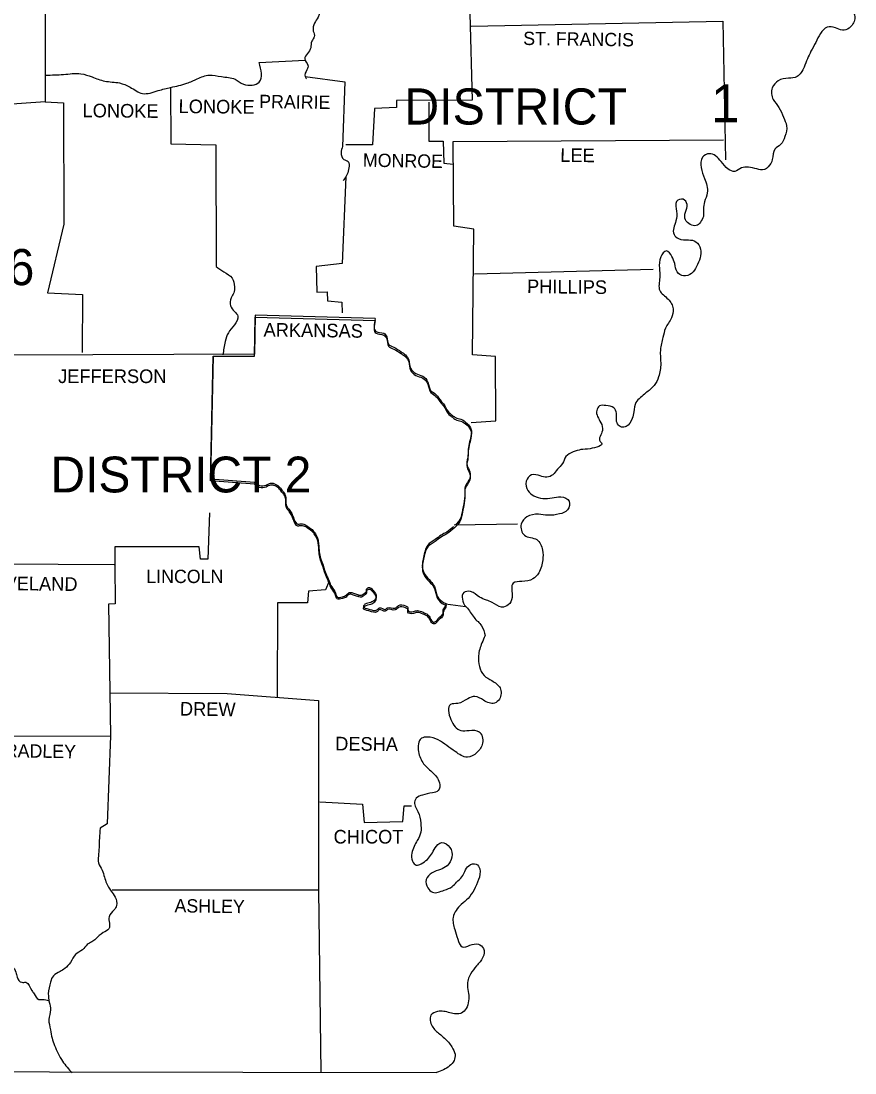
# Model space of a CAD drawing. Extents: x 166 to 3995, y -61 to 2074.
# Drawn here: x 2999.8 to 3257.2, y 1432.7 to 1757.5 of the extents above; entities that cross this region are included whole.
import ezdxf

# ---------------------------------------------------------------- set-up
doc = ezdxf.new("R2010")
doc.units = 0
for name, color, linetype in [('1', 7, 'Continuous'), ('2', 7, 'Continuous'), ('3', 7, 'Continuous')]:
    doc.layers.add(name, color=color, linetype=linetype)

msp = doc.modelspace()

# ---------------------------------------------------------------- linework, layer by layer
at = {"layer": '1'}
msp.add_line((3133.42, 1601.94), (3152.99, 1602.24), dxfattribs=at)
for points in [[(3000.75, 1956.03), (3000.95, 1932.74), (2999.28, 1932.64), (2999.58, 1908.28), (2992.73, 1907.3), (2993.32, 1900.75), (2995.66, 1897.71), (2995.47, 1889.98), (2982.16, 1889.5), (2981.67, 1877.56), (2969.54, 1877.17), (2968.95, 1862.69), (2969.64, 1861.51), (2969.93, 1838.42), (2990.87, 1837.05), (2990.58, 1785.49), (3007.21, 1785), (3007.21, 1732.56), (2994.1, 1731.58), (2993.12, 1720.04), (2971.11, 1719.94)], [(3137.53, 1786.66), (3139, 1733.05), (3115.71, 1732.95), (3115.62, 1730.8), (3108.87, 1730.41), (3108.28, 1719.25), (3100.06, 1719.25)], [(3138.71, 1755.85), (3216.39, 1757.41)], [(3216.39, 1757.41), (3217.18, 1714.56)], [(3073.25, 1744.69), (3087.44, 1745.38)], [(3087.44, 1740.29), (3099.67, 1738.72), (3098.98, 1718.76)], [(3045.86, 1737.06), (3046.05, 1719.55), (3059.85, 1719.25), (3059.95, 1681.68)], [(3007.21, 1732.56), (3012.88, 1732.17), (3012.98, 1694.79), (3007.89, 1673.56), (3018.75, 1673.07), (3018.66, 1655.07)], [(3125.69, 1732.46), (3125.6, 1720.33), (3130.1, 1720.33), (3130.29, 1713.58), (3133.13, 1713.28)], [(3138.71, 1633.54), (3146.34, 1634.03), (3146.24, 1653.9), (3139.1, 1654.38), (3139.49, 1693.23), (3133.33, 1694.11), (3133.13, 1720.23), (3216.59, 1720.82)], [(3100.06, 1709.37), (3098.89, 1682.56), (3090.86, 1681.68), (3091.06, 1673.76), (3094.29, 1673.85), (3094.39, 1671.11), (3098.79, 1670.63), (3098.89, 1667.4)], [(3139.69, 1679.43), (3194.87, 1680.8)], [(3109.06, 1665.64), (3072.08, 1666.61), (3071.88, 1654.58), (2997.03, 1654.29)], [(3059.06, 1653.99), (3071.88, 1653.99), (3072.08, 1666.03), (3109.06, 1665.05)], [(3059.06, 1653.99), (3058.28, 1616.13), (3071.88, 1615.05)], [(3071.88, 1614.47), (3058.28, 1615.54), (3059.06, 1653.99)], [(3057.99, 1605.66), (3057.4, 1591.28), (3055.15, 1591.28), (3054.76, 1595.09), (3028.73, 1595.09), (3028.73, 1589.61)], [(2993.9, 1589.91), (3028.54, 1589.71)], [(3028.73, 1589.71), (3028.83, 1577.48), (3026.78, 1577.38), (3027.36, 1536.78)], [(3094.87, 1584.53), (3093.7, 1581.88), (3088.51, 1581.4), (3088.22, 1577.87), (3078.93, 1577.87), (3078.83, 1548.62)], [(3105.83, 1580.22), (3106.13, 1580.51), (3106.42, 1580.81), (3106.42, 1580.81)], [(3027.07, 1550.09), (3063.37, 1549.79), (3091.55, 1547.64)], [(3091.55, 1547.64), (3091.55, 1489.13), (3092.33, 1432.87)], [(2983.14, 1536.68), (3027.36, 1536.78)], [(3027.36, 1536.78), (3026.39, 1509.58), (3024.23, 1508.21)], [(3092.04, 1516.43), (3105.15, 1515.65), (3105.73, 1509.97), (3117.57, 1510.36), (3118.06, 1515.16), (3120.31, 1515.16)], [(2769.26, 1512.61), (2769.46, 1433.46), (3128.04, 1432.87)], [(3027.95, 1489.23), (3091.55, 1489.23)]]:
    msp.add_lwpolyline(points, dxfattribs=at)
for points in [[(3099.86, 1798.01), (3099.37, 1794.79), (3097.52, 1793.91), (3095.36, 1791.75), (3094.87, 1789.8), (3093.11, 1789.01), (3091.45, 1786.96), (3090.37, 1784.12), (3090.37, 1781.19), (3091.06, 1777.86), (3093.5, 1776.98), (3094.68, 1775.02), (3094.48, 1772.97), (3096.83, 1771.6), (3097.22, 1770.42), (3096.83, 1769.15), (3095.75, 1765.53), (3095.85, 1763.09), (3095.66, 1762.01), (3093.02, 1761.32), (3091.45, 1758.68), (3090.37, 1756.82), (3089.98, 1754.38), (3090.28, 1752.62), (3089.49, 1751.25), (3089.2, 1749.19), (3088.22, 1747.43), (3087.34, 1745.77), (3088.32, 1743.81), (3088.03, 1742.44), (3087.44, 1740.29), (3087.93, 1739.6)], [(3252.89, 1794.1), (3253.28, 1791.26), (3251.62, 1788.23), (3251.03, 1785.2), (3251.32, 1782.16), (3248.19, 1780.5), (3245.45, 1778.54), (3247.02, 1776.2), (3249.95, 1774.04), (3252.89, 1772.38), (3254.75, 1770.72), (3255.24, 1766.71), (3255.72, 1764.16), (3256.7, 1760.64), (3257.09, 1758.19), (3255.33, 1755.26), (3253.28, 1754.67), (3251.13, 1755.36), (3248.58, 1755.55), (3246.53, 1753.59), (3245.06, 1750.86), (3243.59, 1748.12), (3242.52, 1745.77), (3241.44, 1743.22), (3239.29, 1740.29), (3236.65, 1739.8), (3233.51, 1739.02), (3231.66, 1736.86), (3231.95, 1733.24), (3233.71, 1730.8), (3235.08, 1727.76), (3236.06, 1725.12), (3235.57, 1721.8), (3234.2, 1719.35), (3232.44, 1717.88), (3231.66, 1714.75), (3230.38, 1712.4), (3229.21, 1711.62), (3226.86, 1711.82), (3224.32, 1712.31), (3222.16, 1712.11), (3220.11, 1711.03), (3218.06, 1711.72), (3215.9, 1714.07), (3214.14, 1715.83), (3212.19, 1716.51), (3210.13, 1715.44), (3209.74, 1712.21), (3210.72, 1708.88), (3211.6, 1704.38), (3210.72, 1701.64), (3210.42, 1697.14)], [(3007.4, 1740.78), (3012.88, 1740.97), (3018.26, 1741.17), (3021.69, 1740.19), (3025.6, 1738.92), (3030.2, 1738.33), (3033.43, 1737.06), (3037.25, 1735.1), (3042.14, 1735.98), (3045.95, 1736.96), (3050.94, 1738.23), (3054.17, 1739.6), (3057.89, 1740.78), (3061.61, 1740.29), (3065.82, 1739.51), (3068.46, 1737.94), (3073.25, 1738.63), (3073.25, 1744.69)], [(3098.98, 1718.76), (3098.59, 1716.81), (3099.37, 1714.75), (3100.74, 1714.07), (3100.94, 1712.11), (3100.45, 1710.15), (3100.06, 1709.37), (3099.18, 1708.2)], [(3210.42, 1697.14), (3208.17, 1694.3), (3204.85, 1696.06), (3204.85, 1698.41), (3205.34, 1700.86), (3204.16, 1702.42), (3202.11, 1701.74), (3202.11, 1698.71), (3201.91, 1695.77), (3201.32, 1691.56), (3202.69, 1690.29), (3205.83, 1689.9), (3208.08, 1689.31), (3209.45, 1687.06), (3209.35, 1684.32), (3208.27, 1681.68), (3206.71, 1679.53), (3204.26, 1678.75), (3202.3, 1680.02), (3201.52, 1682.56), (3200.64, 1684.81), (3198.98, 1686.48), (3197.22, 1684.62), (3196.82, 1681.19), (3196.92, 1678.26), (3196.92, 1674.25), (3199.47, 1671.6), (3201.03, 1668.57), (3200.54, 1665.83), (3198.68, 1662.6), (3197.9, 1659.77), (3197.12, 1655.95), (3197.22, 1651.74), (3196.53, 1647.63), (3195.16, 1644.89), (3192.62, 1642.64), (3190.95, 1641.18), (3189.58, 1639.71), (3188.9, 1636.77), (3188.41, 1634.72), (3186.55, 1632.27), (3185.08, 1632.08), (3183.91, 1633.05), (3183.52, 1634.72), (3183.52, 1636.38), (3182.74, 1638.04), (3180.29, 1638.73), (3178.33, 1638.63), (3177.45, 1637.26), (3178.72, 1633.45), (3179.21, 1631), (3178.53, 1627.67), (3178.92, 1627.28), (3175.4, 1625.42), (3172.56, 1625.13), (3170.21, 1624.44), (3167.96, 1622.98), (3166.88, 1620.82), (3165.32, 1619.06), (3163.95, 1617.4), (3162.09, 1616.62), (3160.04, 1617.01), (3157.3, 1617.3), (3155.73, 1615.35), (3156.22, 1612.51), (3158.08, 1610.85), (3160.82, 1610.06), (3163.66, 1610.26), (3166.4, 1610.55), (3168.94, 1609.18), (3168.45, 1606.54), (3166, 1605.27), (3162.38, 1604.88), (3159.45, 1605.17), (3155.93, 1604.39), (3154.17, 1602.14), (3155.14, 1598.71), (3158.96, 1597.34), (3160.72, 1594.11), (3160.82, 1591.08), (3159.55, 1587.07), (3157.79, 1585.21), (3154.36, 1584.43), (3151.72, 1583.94), (3151.33, 1579.44), (3150.15, 1577.19), (3148.1, 1576.5), (3145.16, 1577.97), (3143.4, 1578.66), (3141.25, 1579.63), (3138.51, 1581.3), (3136.46, 1581), (3137.04, 1576.7), (3137.24, 1576.5), (3139.59, 1573.27), (3141.94, 1570.73), (3143.01, 1567.7)], [(3059.95, 1681.68), (3062.39, 1680.02), (3064.93, 1678.06), (3065.62, 1675.42), (3065.42, 1673.56), (3064.64, 1672), (3064.45, 1669.55), (3065.62, 1667.79), (3066.7, 1666.32), (3065.62, 1663.68), (3063.76, 1661.23), (3062.78, 1658.49), (3062.1, 1654.38)], [(3109.06, 1665.64), (3109.35, 1661.62), (3111.7, 1661.04), (3112.68, 1659.96), (3113.17, 1657.71), (3114.83, 1656.73), (3117.08, 1655.36), (3118.45, 1654.38), (3119.43, 1652.82), (3120.02, 1650.27), (3121.58, 1648.61), (3123.74, 1647.83), (3125.3, 1645.97), (3126.28, 1643.33), (3127.85, 1642.15), (3129.41, 1640.1), (3130.19, 1639.22), (3131.56, 1636.87), (3132.93, 1635.7), (3133.91, 1635.01), (3135.48, 1634.52), (3137.43, 1633.25), (3138.71, 1631.29), (3138.71, 1629.83), (3138.22, 1627.58), (3137.83, 1625.23), (3137.63, 1622.59), (3137.43, 1620.24), (3138.32, 1618.28), (3137.83, 1615.35), (3136.85, 1613.78), (3136.75, 1611.63), (3136.46, 1608.4), (3136.07, 1606.54), (3135.18, 1603.51), (3133.91, 1601.94)], [(3109.06, 1665.05), (3109.35, 1661.04), (3111.7, 1660.45), (3112.68, 1659.37), (3113.17, 1657.12), (3114.83, 1656.15), (3117.08, 1654.78), (3118.45, 1653.8), (3119.43, 1652.23), (3120.02, 1649.69), (3121.58, 1648.02), (3123.74, 1647.24), (3125.3, 1645.38), (3126.28, 1642.74), (3127.85, 1641.57), (3129.41, 1639.51), (3130.19, 1638.63), (3131.56, 1636.28), (3132.93, 1635.11), (3133.91, 1634.42), (3135.48, 1633.94), (3137.43, 1632.66), (3138.71, 1630.71), (3138.71, 1629.24), (3138.22, 1626.99), (3137.83, 1624.64), (3137.63, 1622), (3137.43, 1619.65), (3138.32, 1617.69), (3137.83, 1614.76), (3136.85, 1613.19), (3136.75, 1611.04), (3136.46, 1607.81), (3136.07, 1605.95), (3135.18, 1602.92), (3133.62, 1601.06)], [(3071.88, 1615.05), (3073.35, 1614.07), (3075.4, 1614.17), (3076.77, 1614.76), (3077.85, 1614.66), (3079.32, 1613.78), (3080.3, 1612.61), (3080.98, 1611.73), (3081.47, 1610.36), (3081.47, 1609.08), (3081.96, 1607.32), (3082.55, 1606.64), (3083.33, 1605.37), (3083.82, 1604.19), (3084.11, 1603.41), (3085.19, 1602.14), (3086.17, 1602.24), (3087.05, 1602.14), (3088.22, 1601.45), (3089.98, 1600.08), (3090.28, 1599.69), (3091.45, 1597.15), (3091.65, 1595.58), (3091.84, 1593.53), (3092.23, 1591.57), (3093.02, 1589.42), (3093.41, 1587.95), (3094.29, 1585.9), (3094.87, 1584.53), (3095.66, 1582.76), (3096.83, 1580.81), (3097.32, 1579.63), (3098.98, 1579.73), (3100.16, 1580.22), (3101.04, 1581), (3102.11, 1580.91), (3103.29, 1580.51), (3104.85, 1580.22), (3105.83, 1580.81), (3106.32, 1581.2), (3106.42, 1582.08), (3107.3, 1582.57), (3108.28, 1581.88), (3109.35, 1580.32), (3109.35, 1579.34), (3108.96, 1578.75), (3107.69, 1577.97), (3105.93, 1577.38), (3105.44, 1576.7), (3107.1, 1575.92), (3109.75, 1575.72), (3110.43, 1576.31), (3112.19, 1575.82), (3112.88, 1576.31), (3115.23, 1576.21), (3116.3, 1576.99), (3118.45, 1576.89), (3119.14, 1576.41), (3119.14, 1575.52), (3120.9, 1575.13), (3122.17, 1575.43), (3123.84, 1574.94), (3125.3, 1574.15), (3126.09, 1573.08), (3127.06, 1571.9), (3127.94, 1572.2), (3128.63, 1573.08), (3130.1, 1574.64), (3130.1, 1575.62), (3130.49, 1576.31), (3130.98, 1577.29)], [(3130.98, 1576.7), (3130.49, 1575.72), (3130.1, 1575.04), (3130.1, 1574.06), (3128.63, 1572.49), (3127.94, 1571.61), (3127.06, 1571.32), (3126.09, 1572.49), (3125.3, 1573.57), (3123.84, 1574.35), (3122.17, 1574.84), (3120.9, 1574.55), (3119.14, 1574.94), (3119.14, 1575.82), (3118.45, 1576.31), (3116.3, 1576.41), (3115.23, 1575.62), (3112.88, 1575.72), (3112.19, 1575.23), (3110.43, 1575.72), (3109.75, 1575.13), (3107.1, 1575.33), (3105.44, 1576.11), (3105.93, 1576.8), (3107.69, 1577.38), (3108.96, 1578.17), (3109.35, 1578.75), (3109.35, 1579.73), (3108.28, 1581.3), (3107.3, 1581.98), (3106.42, 1581.49), (3106.32, 1580.61), (3105.83, 1580.22), (3104.85, 1579.63), (3103.29, 1579.93), (3102.11, 1580.32), (3101.04, 1580.42), (3100.16, 1579.63), (3098.98, 1579.14), (3097.32, 1579.05), (3096.83, 1580.22), (3095.66, 1582.18), (3094.87, 1583.94), (3094.29, 1585.31), (3093.41, 1587.36), (3093.02, 1588.83), (3092.23, 1590.98), (3091.84, 1592.94), (3091.65, 1594.99), (3091.45, 1596.56), (3090.28, 1599.1), (3089.98, 1599.5), (3088.22, 1600.87), (3087.05, 1601.55), (3086.17, 1601.65), (3085.19, 1601.55), (3084.11, 1602.82), (3083.82, 1603.6), (3083.33, 1604.78), (3082.55, 1606.05), (3081.96, 1606.74), (3081.47, 1608.5), (3081.47, 1609.77), (3080.98, 1611.14), (3080.3, 1612.02), (3079.32, 1613.19), (3077.85, 1614.07), (3076.77, 1614.17), (3075.4, 1613.58), (3073.35, 1613.49), (3071.88, 1614.47)], [(3133.23, 1601.35), (3131.17, 1599.69), (3129.41, 1598.71), (3127.55, 1597.34), (3125.3, 1595.68), (3124.23, 1592.84), (3123.64, 1588.93), (3124.42, 1586.58), (3126.18, 1584.53), (3127.36, 1582.86), (3128.24, 1579.93), (3130.39, 1577.87), (3131.08, 1577.58)], [(3133.62, 1601.06), (3131.17, 1599.1), (3129.41, 1598.13), (3127.55, 1596.76), (3125.3, 1595.09), (3124.23, 1592.26), (3123.64, 1588.34), (3124.42, 1585.99), (3126.18, 1583.94), (3127.36, 1582.28), (3128.24, 1579.34), (3130.39, 1577.29), (3131.08, 1576.99)], [(3143.01, 1567.7), (3142.03, 1565.45), (3140.96, 1561.53), (3141.25, 1558.21), (3142.72, 1555.37), (3145.07, 1553.8), (3147.61, 1551.55), (3147.41, 1548.13), (3145.95, 1546.86), (3142.52, 1547.74), (3139.88, 1548.91), (3137.63, 1548.23), (3134.6, 1546.76), (3132.35, 1546.47), (3132.45, 1541.77), (3135.48, 1538.44), (3138.12, 1538.44), (3141.15, 1538.05), (3142.23, 1534.53), (3140.47, 1531.59), (3137.53, 1530.13), (3133.81, 1531.89), (3131.17, 1533.75), (3128.53, 1535.51), (3125.2, 1536.39), (3123.35, 1536), (3122.47, 1531.89), (3124.03, 1528.17), (3126.57, 1525.63), (3128.92, 1522.3), (3128.53, 1519.85), (3126.77, 1519.17), (3123.64, 1518.48), (3121.78, 1517.51), (3121.29, 1516.72), (3122.27, 1513.4), (3123.15, 1509.78), (3123.15, 1507.04), (3122.07, 1504.49), (3120.41, 1500.58), (3120.61, 1498.03), (3121.78, 1496.86), (3123.25, 1497.25), (3125.2, 1498.62), (3126.48, 1500.19), (3127.55, 1502.14), (3129.61, 1503.81), (3132.15, 1502.34), (3132.74, 1499.31), (3131.27, 1496.67), (3129.22, 1495.49), (3126.67, 1494.51), (3124.81, 1492.36), (3125.3, 1489.82), (3126.77, 1488.45), (3130.39, 1489.13), (3132.84, 1490.21), (3134.21, 1491.58), (3135.87, 1493.24), (3136.75, 1494.9), (3138.02, 1496.67), (3140.27, 1497.15), (3141.35, 1495.69), (3140.96, 1492.36), (3139.59, 1489.23), (3137.73, 1486.59), (3135.67, 1484.73), (3133.13, 1480.72), (3133.62, 1477), (3134.6, 1473.97), (3135.97, 1471.62), (3138.32, 1472.11), (3140.96, 1472.4), (3142.52, 1471.13), (3142.33, 1468.39), (3140.37, 1465.75), (3138.51, 1463.2), (3137.53, 1459.68), (3137.92, 1457.24), (3137.92, 1454.98), (3137.14, 1452.54), (3135.77, 1451.17), (3132.15, 1451.27), (3128.34, 1451.66), (3126.28, 1450.48), (3126.67, 1447.16), (3128.92, 1444.71), (3130.49, 1443.44), (3132.74, 1440.7), (3133.72, 1438.45), (3133.42, 1436.49), (3132.05, 1434.83), (3128.04, 1432.87)], [(3024.23, 1508.21), (3023.94, 1505.18), (3023.84, 1502.34), (3023.65, 1499.6), (3023.65, 1497.55), (3024.82, 1495.3), (3025.51, 1493.14), (3026.19, 1491.28), (3027.56, 1488.84), (3028.83, 1486.98), (3029.22, 1484.34), (3028.44, 1482.97), (3026.97, 1480.91), (3026.87, 1477.19), (3025.11, 1476.02), (3022.86, 1474.06), (3021.59, 1473.18), (3020.22, 1472.3), (3018.75, 1470.74), (3016.6, 1469.27), (3015.04, 1466.82), (3013.28, 1464.96), (3011.81, 1463.99), (3009.75, 1462.71), (3008.87, 1460.76), (3008.19, 1457.14), (3008.48, 1454.5), (3008.87, 1452.15), (3008.38, 1449.21), (3008.87, 1445.98), (3009.36, 1443.44), (3010.14, 1441.19), (3011.22, 1438.65), (3012.59, 1436.3), (3015.53, 1432.68)], [(2926.69, 1485.61), (2928.25, 1486.69), (2929.72, 1487.27), (2931.19, 1486.98), (2932.75, 1486.78), (2934.12, 1486.98), (2935.88, 1486.69), (2937.35, 1485.8), (2939.01, 1485.12), (2940.68, 1485.12), (2942.14, 1485.12), (2943.42, 1484.24), (2945.77, 1484.34), (2947.72, 1485.12), (2949.68, 1485.71), (2952.32, 1486), (2954.67, 1484.34), (2956.33, 1482.97), (2957.7, 1481.4), (2958.68, 1479.64), (2959.76, 1478.66), (2961.52, 1477.98), (2962.89, 1477.68), (2964.55, 1477.19), (2965.43, 1476.8), (2966.21, 1474.94), (2967.49, 1472.4), (2969.93, 1471.52), (2972.96, 1472.69), (2975.41, 1473.38), (2977.17, 1473.97), (2978.25, 1474.36), (2979.23, 1474.46), (2978.93, 1474.65), (2980.11, 1474.94), (2981.18, 1474.16), (2981.87, 1473.09), (2983.04, 1471.52), (2984.12, 1470.15), (2985.19, 1469.66), (2986.27, 1470.25), (2987.74, 1469.76), (2989.01, 1469.27), (2990.48, 1468.88), (2991.75, 1468.78), (2993.41, 1468.39), (2994.69, 1467.7), (2995.86, 1467.02), (2997.03, 1465.75), (2998.21, 1463.79), (2998.6, 1462.23), (2999.97, 1460.66), (3001.24, 1460.66), (3003.1, 1458.12), (3003.78, 1457.14), (3005.25, 1455.38), (3006.33, 1455.38), (3008.38, 1454.98)]]:
    msp.add_spline(points, degree=3, dxfattribs=at)
at = {"layer": '3'}
msp.add_line((3130.78, 1577.48), (3136.95, 1576.7), dxfattribs=at)

# ---------------------------------------------------------------- texts
at = {"layer": '1'}
msp.add_text('1', height=11.74, dxfattribs=at).set_placement((3212.77, 1726.2))
at = {"layer": '2'}
for s, height, rotation, p in [('ST. FRANCIS', 4.1081, 359.2216, (3154.75, 1750.07)), ('PRAIRIE', 4.109, 359.2116, (3073.25, 1730.6)), ('LONOKE', 4.207, 359.4974, (3018.75, 1727.76)), ('LONOKE', 4.207, 359.4974, (3048.4, 1729.04)), ('LEE', 4.207, 359.4327, (3166.2, 1713.97)), ('MONROE', 4.108, 359.0331, (3105.25, 1712.5)), ('PHILLIPS', 4.206, 359.3179, (3155.93, 1673.46)), ('ARKANSAS', 4.206, 359.2678, (3074.62, 1660.06)), ('CLEVELAND', 4.207, 359.3377, (2983.73, 1581.88)), ('DREW', 4.206, 359.2258, (3048.79, 1543.04)), ('DESHA', 4.206, 359.3704, (3096.73, 1532.28)), ('BRADLEY', 4.108, 359.1449, (2991.07, 1530.22)), ('ASHLEY', 4.109, 359.2361, (3047.13, 1482.28))]:
    msp.add_text(s, height=height, rotation=rotation, dxfattribs=at).set_placement(p)
for s, height, p in [('JEFFERSON', 4.207, (3011.22, 1645.68)), ('LINCOLN', 4.109, (3038.42, 1583.94)), ('CHICOT', 4.207, (3096.24, 1503.51))]:
    msp.add_text(s, height=height, dxfattribs=at).set_placement(p)
at = {"layer": '3'}
for s, height, p in [('DISTRICT', 11.154, (3118.06, 1725.51)), ('DISTRICT 6', 11.154, (2922.67, 1675.91)), ('DISTRICT 2', 11.056, (3008.87, 1611.92))]:
    msp.add_text(s, height=height, dxfattribs=at).set_placement(p)

doc.saveas('drawing.dxf')
